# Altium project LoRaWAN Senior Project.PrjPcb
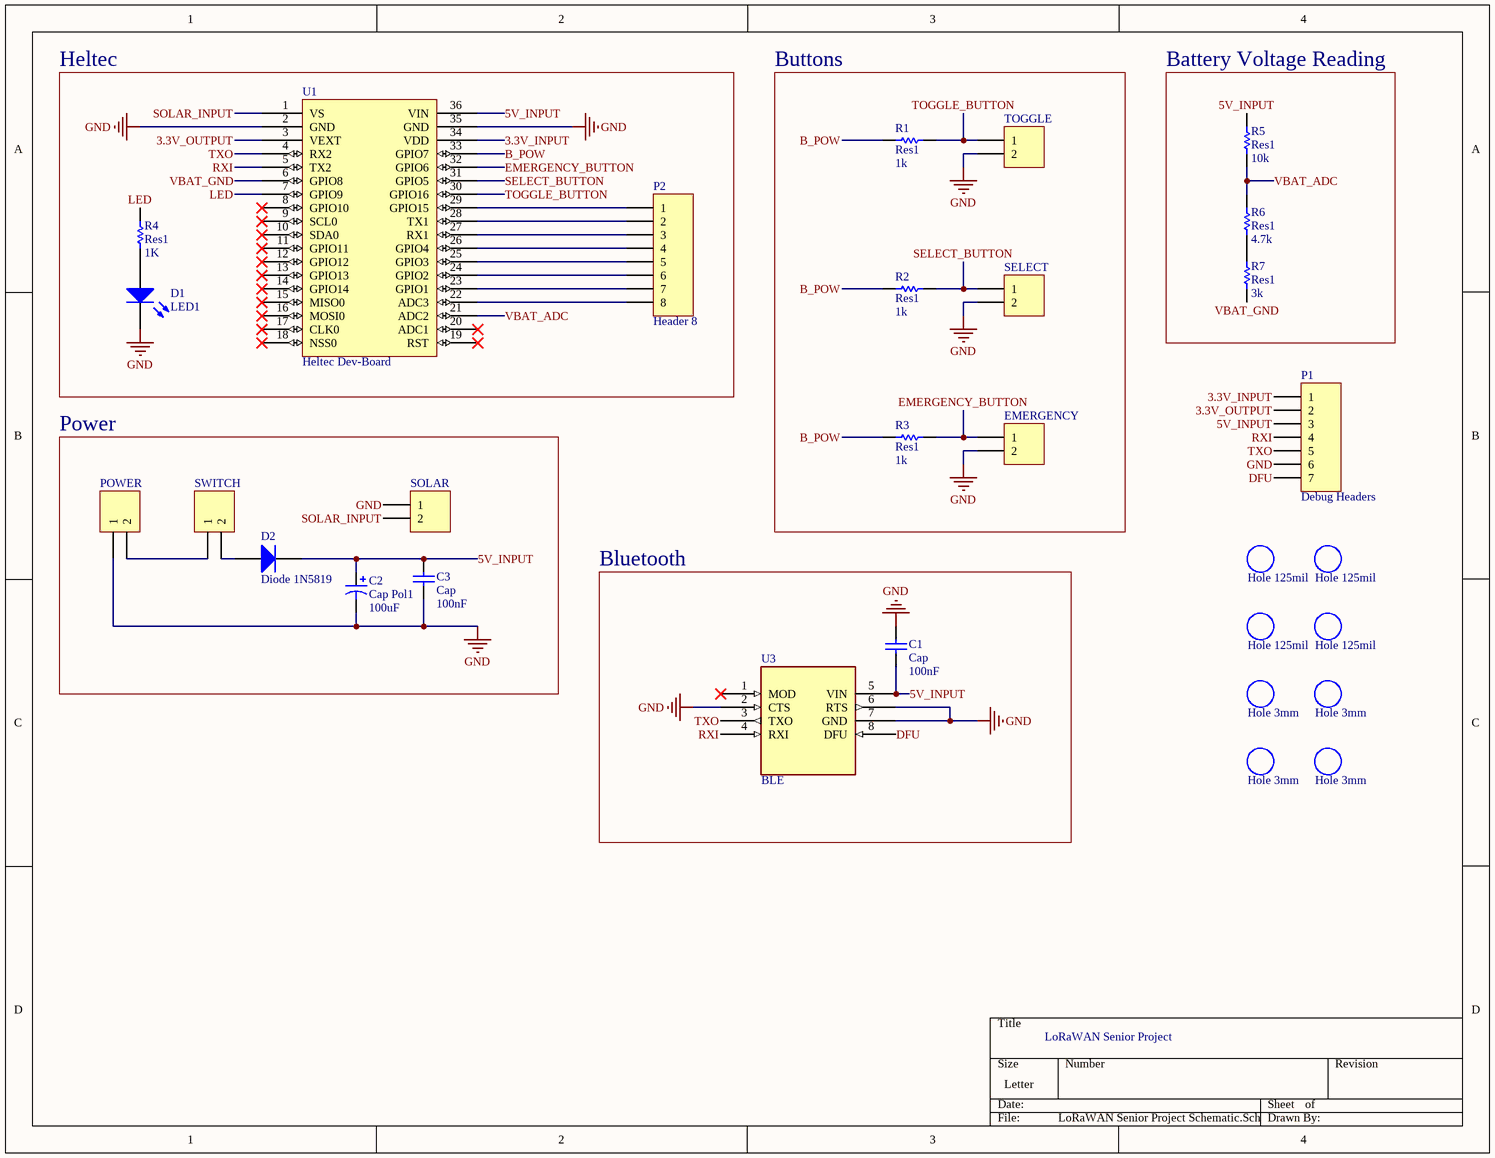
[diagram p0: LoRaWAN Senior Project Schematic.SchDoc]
1 sheet, 30 parts. Net scope: global (net labels, ports and power ports of the same name join across sheets).
Board file: LoRaWAN Senior Project PCB.PcbDoc

## Sheet LoRaWAN Senior Project Schematic.SchDoc
size Letter; SheetNumber: 1; SheetTotal: 1; SPICEModelCacheQPXBXETC: <root> / <DocumentId>QPXBXETC</DocumentId> / <CacheFrame Number="0"> / <Model Name="cap" Kind="MDL"> / <Text>*Default semiconductor capacitor / .MODEL CAP C()</Text> / </Model> / <Model Name="led1" Kind="MDL"> / <Text>*Typ RED GaAs LED: Vf=1.7V Vr=4V If=40mA trr=3uS / *LED Pinout: 1=A, 2=K / .MODEL LED1 D (IS=93.2P RS=42M N=3.73 BV=4 IBV=10U / + CJO=2.97P VJ=.75 M=.333 TT=4.32U)</Text> / </Model> / <Model Name="1n4001" Kind="MDL"> / <Text>*1N4001 MCE 8-16-95 / *50V 1A Si GenPurpose Diode pkg:DIODE0.4 1,2 / .MODEL 1N4001 D(IS=2.55E-9 RS=0.042 N=1.75 TT=5.76E-6 CJO=1.85E-11 / + VJ=0.75 M=0.333 BV=50 IBV=1E-5 )</Text> / </Model> / </CacheFrame> / </root>

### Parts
C1  Cap  value 100nF  [RAD-0.1]
C2  Cap Pol1  value 100uF  [RAD-0.2]
C3  Cap  value 100nF  [RAD-0.1]
D1  LED1  [LED-1]
D2  Diode 1N5819  [DO-41]
EMERGENCY  Button Port  [CON2screw]  (value not drawn)
H1  Hole 125mil  [Hole 125mil]
H2  Hole 125mil  [Hole 125mil]
H3  Hole 125mil  [Hole 125mil]
H4  Hole 125mil  [Hole 125mil]
H5  Hole 3mm  [Hole 3mm]
H6  Hole 3mm  [Hole 3mm]
H7  Hole 3mm  [Hole 3mm]
H8  Hole 3mm  [Hole 3mm]
P1  Debug Headers  [HDR1X7]
P2  Header 8  [HDR1X8]
POWER  Power Port  [CON2screw]  (value not drawn)
R1  Res1  value 1k  [RESISTOR]
R2  Res1  value 1k  [RESISTOR]
R3  Res1  value 1k  [RESISTOR]
R4  Res1  value 1K  [AXIAL-0.3]
R5  Res1  value 10k  [RESISTOR]
R6  Res1  value 4.7k  [RESISTOR]
R7  Res1  value 3k  [RESISTOR]
SELECT  Button Port  [CON2screw]  (value not drawn)
SOLAR  Solar Port  [CON2screw]  (value not drawn)
SWITCH  Switch Port  [CON2screw]  (value not drawn)
TOGGLE  Button Port  [CON2screw]  (value not drawn)
U1  Heltec Dev-Board  [HELTEC]
U3  BLE  [Adafruit BLE]

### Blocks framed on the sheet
Heltec: D1 P2 R4 U1
Buttons: EMERGENCY R1-R3 SELECT TOGGLE
Battery Voltage Reading: R5-R7
Power: C2 C3 D2 POWER SOLAR SWITCH
Bluetooth: C1 U3

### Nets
GND: C1.1 C2.2 C3.1 D1.2(K) EMERGENCY.2 P1.6 POWER.1 SELECT.2 SOLAR.1 TOGGLE.2 U1.2(GND) U1.35(GND) U3.2(CTS) U3.6(RTS) U3.7(GND)
3.3V_INPUT: P1.1 U1.34(VDD)
3.3V_OUTPUT: P1.2 U1.3(VEXT)
5V_INPUT: C1.2 C2.1 C3.2 D2.2(K) P1.3 R5.2 U1.36(VIN) U3.5(VIN)
B_POW: R1.1 R2.1 R3.1 U1.33(GPIO7)
DFU: P1.7 U3.8(DFU)
EMERGENCY_BUTTON: EMERGENCY.1 R3.2 U1.32(GPIO6)
LED: R4.2 U1.7(GPIO9)
RXI: P1.4 U1.5(TX2) U3.4(RXI)
SELECT_BUTTON: R2.2 SELECT.1 U1.31(GPIO5)
SOLAR_INPUT: SOLAR.2 U1.1(VS)
TOGGLE_BUTTON: R1.2 TOGGLE.1 U1.30(GPIO16)
TXO: P1.5 U1.4(RX2) U3.3(TXO)
VBAT_ADC: R5.1 R6.2 U1.21(ADC2)
VBAT_GND: R7.1 U1.6(GPIO8)
NetD1_1: D1.1(A) R4.1
NetD2_1: D2.1(A) SWITCH.2
NetP2_1: P2.1 U1.29(GPIO15)
NetP2_2: P2.2 U1.28(TX1)
NetP2_3: P2.3 U1.27(RX1)
NetP2_4: P2.4 U1.26(GPIO4)
NetP2_5: P2.5 U1.25(GPIO3)
NetP2_6: P2.6 U1.24(GPIO2)
NetP2_7: P2.7 U1.23(GPIO1)
NetP2_8: P2.8 U1.22(ADC3)
NetPOWER_2: POWER.2 SWITCH.1
NetR6_1: R6.1 R7.2

Not connected (* = marked no-connect by the designer): U1 8(GPIO10)* 9(SCL0)* 10(SDA0)* 11(GPIO11)* 12(GPIO12)* 13(GPIO13)* 14(GPIO14)* 15(MISO0)* 16(MOSI0)* 17(CLK0)* 18(NSS0)* 19(RST)* 20(ADC1)*; U3 1(MOD)*

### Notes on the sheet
- LoRaWAN Senior Project

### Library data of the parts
C1 C3 = Cap: Capacitor
C2 = Cap Pol1: Polarized Capacitor (Radial)
D1 = LED1: Typical RED GaAs LED
D2 = Diode 1N4001: 1 Amp General Purpose Rectifier
EMERGENCY POWER SELECT SOLAR SWITCH TOGGLE = Power
P1 = Header 7: Header, 7-Pin
P2 = Header 8: Header, 8-Pin
R1-R7 = Res1: Resistor
U3 = Adafruit BLE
